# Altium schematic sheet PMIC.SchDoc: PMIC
size A3; Date: Not used; ApprovedBy: Not used; CheckedBy: Not used; Author: Not used; CompanyName: STMicroelectronics; DrawnBy: Not used; Engineer: Not used; Organization: Not used; Address1: Not used; Address2: Not used; Address3: Not used; Address4: Not used; DocumentNumber: 4; Revision: Not used; SheetNumber: 4; SheetTotal: 7
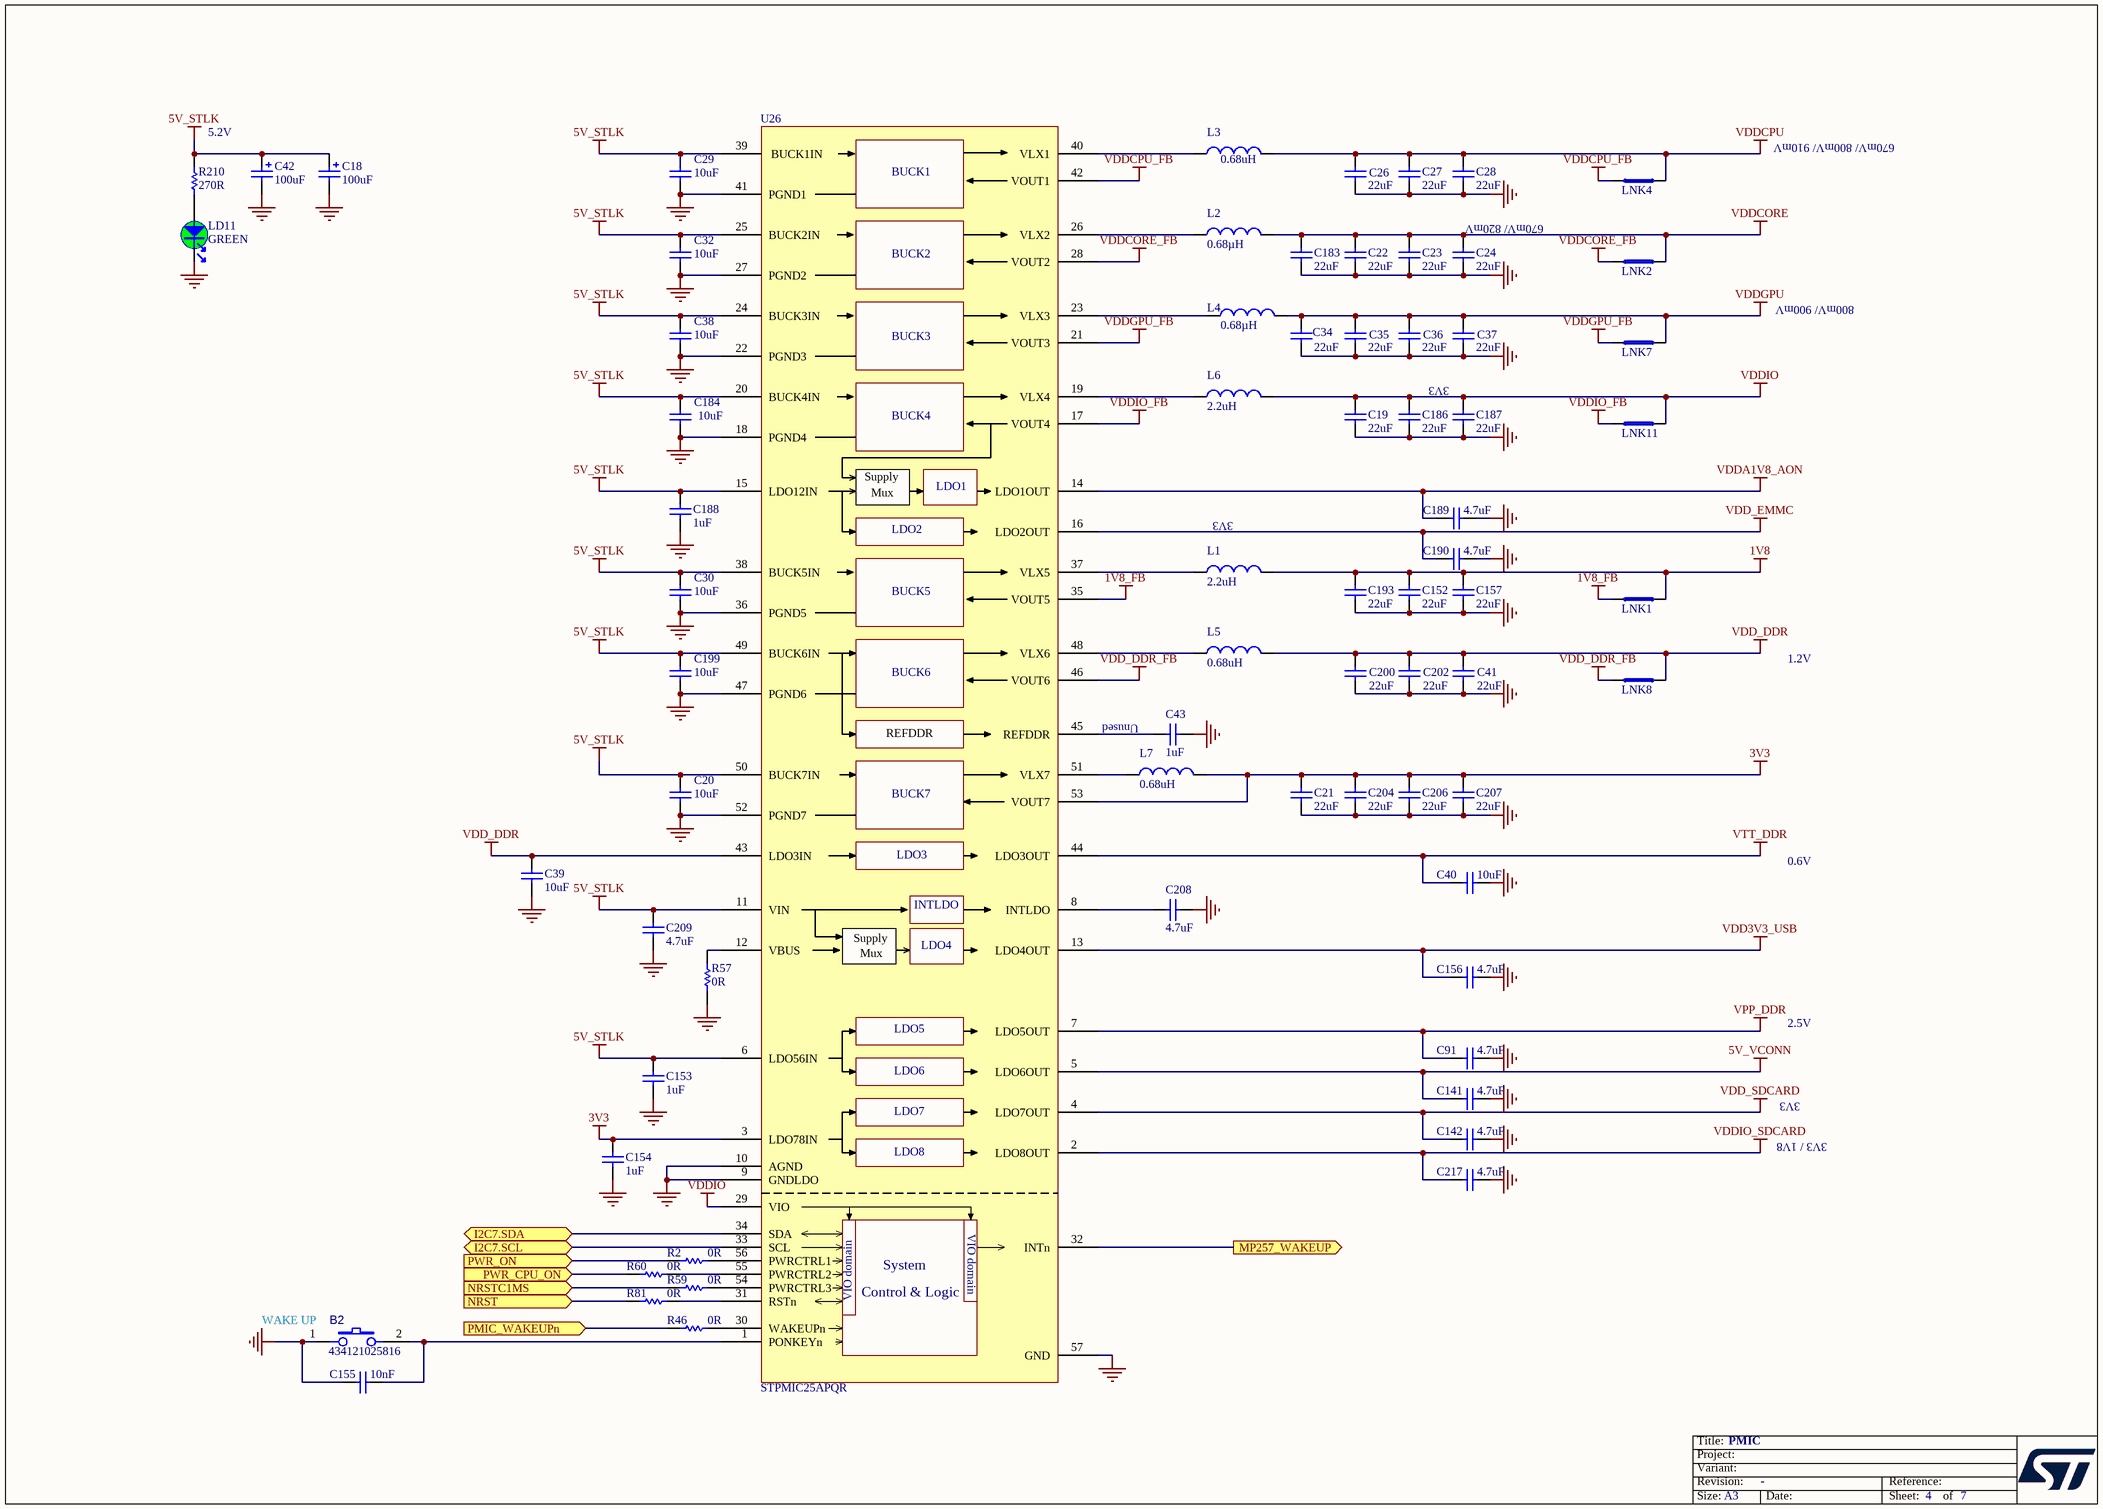
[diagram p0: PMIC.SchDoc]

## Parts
B2  value 434121025816  [SWI_WE_434121025816]  (hidden comment: SW_PUSH_SMD_2P)
C18  value 100uF  [CPOL_TCJ-B_1210_H210]  (hidden comment: Cap_POL_TANA)
C19  value 22uF  [C0805]  (hidden comment: Capacitor)
C20  value 10uF  [C0603]  (hidden comment: Capacitor)
C21  value 22uF  [C0805]  (hidden comment: Capacitor)
C22  value 22uF  [C0603]  (hidden comment: Capacitor)
C23  value 22uF  [C0603]  (hidden comment: Capacitor)
C24  value 22uF  [C0603]  (hidden comment: Capacitor)
C26  value 22uF  [C0603]  (hidden comment: Capacitor)
C27  value 22uF  [C0603]  (hidden comment: Capacitor)
C28  value 22uF  [C0603]  (hidden comment: Capacitor)
C29  value 10uF  [C0603]  (hidden comment: Capacitor)
C30  value 10uF  [C0603]  (hidden comment: Capacitor)
C32  value 10uF  [C0603]  (hidden comment: Capacitor)
C34  value 22uF  [C0603]  (hidden comment: Capacitor)
C35  value 22uF  [C0603]  (hidden comment: Capacitor)
C36  value 22uF  [C0603]  (hidden comment: Capacitor)
C37  value 22uF  [C0603]  (hidden comment: Capacitor)
C38  value 10uF  [C0603]  (hidden comment: Capacitor)
C39  value 10uF  [C0402]  (hidden comment: Capacitor)
C40  value 10uF  [C0402]  (hidden comment: Capacitor)
C41  value 22uF  [C0603]  (hidden comment: Capacitor)
C42  value 100uF  [CPOL_TCJ-B_1210_H210]  (hidden comment: Cap_POL_TANA)
C43  value 1uF  [C0402]  (hidden comment: Capacitor)
C91  value 4.7uF  [C0402]  (hidden comment: Capacitor)
C141  value 4.7uF  [C0402]  (hidden comment: Capacitor)
C142  value 4.7uF  [C0402]  (hidden comment: Capacitor)
C152  value 22uF  [C0805]  (hidden comment: Capacitor)
C153  value 1uF  [C0402]  (hidden comment: Capacitor)
C154  value 1uF  [C0402]  (hidden comment: Capacitor)
C155  value 10nF  [C0402]  (hidden comment: Capacitor)
C156  value 4.7uF  [C0402]  (hidden comment: Capacitor)
C157  value 22uF  [C0805]  (hidden comment: Capacitor)
C183  value 22uF  [C0603]  (hidden comment: Capacitor)
C184  value 10uF  [C0603]  (hidden comment: Capacitor)
C186  value 22uF  [C0805]  (hidden comment: Capacitor)
C187  value 22uF  [C0805]  (hidden comment: Capacitor)
C188  value 1uF  [C0402]  (hidden comment: Capacitor)
C189  value 4.7uF  [C0402]  (hidden comment: Capacitor)
C190  value 4.7uF  [C0402]  (hidden comment: Capacitor)
C193  value 22uF  [C0805]  (hidden comment: Capacitor)
C199  value 10uF  [C0603]  (hidden comment: Capacitor)
C200  value 22uF  [C0603]  (hidden comment: Capacitor)
C202  value 22uF  [C0603]  (hidden comment: Capacitor)
C204  value 22uF  [C0805]  (hidden comment: Capacitor)
C206  value 22uF  [C0805]  (hidden comment: Capacitor)
C207  value 22uF  [C0805]  (hidden comment: Capacitor)
C208  value 4.7uF  [C0402]  (hidden comment: Capacitor)
C209  value 4.7uF  [C0402]  (hidden comment: Capacitor)
C217  value 4.7uF  [C0402]  (hidden comment: Capacitor)
L1  value 2.2uH  [IND_2016_MURATA_LQM2MPN2R2NG0]  (hidden comment: Inductor)
L2  value 0.68µH  [IND_2520_TOKO_DFE252012P]  (hidden comment: Inductor)
L3  value 0.68uH  [IND_2016_MURATA_LQM2MPN2R2NG0]  (hidden comment: Inductor)
L4  value 0.68µH  [IND_2520_TOKO_DFE252012P]  (hidden comment: Inductor)
L5  value 0.68uH  [IND_2016_MURATA_LQM2MPN2R2NG0]  (hidden comment: Inductor)
L6  value 2.2uH  [IND_2016_MURATA_LQM2MPN2R2NG0]  (hidden comment: Inductor)
L7  value 0.68uH  [IND_2016_MURATA_LQM2MPN2R2NG0]  (hidden comment: Inductor)
LD11  value GREEN  [LED_0603_OSRAM_LG-Q396-PS-35_GREEN_1A2K_H0P4]  (hidden comment: LED_green)
LNK1  link_200  [LINK200]  (value not drawn)  (no BOM)
LNK2  link_200  [LINK200]  (value not drawn)  (no BOM)
LNK4  link_200  [LINK200]  (value not drawn)  (no BOM)
LNK7  link_200  [LINK200]  (value not drawn)  (no BOM)
LNK8  link_200  [LINK200]  (value not drawn)  (no BOM)
LNK11  link_200  [LINK200]  (value not drawn)  (no BOM)
R2  value 0R  [R0402]
R46  value 0R  [R0402]
R57  value 0R  [R0402]
R59  value 0R  [R0402]
R60  value 0R  [R0402]
R81  value 0R  [R0402]
R210  value 270R  [R0402]  (hidden comment: Resistor)
U26  STPMIC25APQR  [ICC_QFN56-EPAD_6P5X6P5_P040]

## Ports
I2C7.SCL (bidir), I2C7.SDA (bidir), MP257_WAKEUP (out), NRST (in), NRSTC1MS (in), PMIC_WAKEUPn (in), PWR_CPU_ON (in), PWR_ON (in)

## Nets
1V8: C152.2 C157.2 C193.2 L1.2 LNK1.2
1V8_FB: LNK1.1 U26.35(VOUT5)
3V3: C21.2 C154.2 C204.2 C206.2 C207.2 L7.2 U26.3(LDO78IN) U26.53(VOUT7)
5V_STLK: C18.1 C20.2 C29.2 C30.2 C32.2 C38.2 C42.1 C153.2 C184.2 C188.2 C199.2 C209.2 R210.1 U26.6(LDO56IN) U26.11(VIN) U26.15(LDO12IN) U26.20(BUCK4IN) U26.24(BUCK3IN) U26.25(BUCK2IN) U26.38(BUCK5IN) U26.39(BUCK1IN) U26.49(BUCK6IN) U26.50(BUCK7IN)
5V_VCONN: C141.1 U26.5(LDO6OUT)
GND: B2.1 C18.2 C19.1 C20.1 C21.1 C22.1 C23.1 C24.1 C26.1 C27.1 C28.1 C29.1 C30.1 C32.1 C34.1 C35.1 C36.1 C37.1 C38.1 C39.1 C40.1 C41.1 C42.2 C43.1 C91.2 C141.2 C142.2 C152.1 C153.1 C154.1 C155.1 C156.1 C157.1 C183.1 C184.1 C186.1 C187.1 C188.1 C189.1 C190.2 C193.1 C199.1 C200.1 C202.1 C204.1 C206.1 C207.1 C208.2 C209.1 C217.2 LD11.2 R57.1 U26.9(GNDLDO) U26.10(AGND) U26.18(PGND4) U26.22(PGND3) U26.27(PGND2) U26.36(PGND5) U26.41(PGND1) U26.47(PGND6) U26.52(PGND7) U26.57(GND)
VDD3V3_USB: C156.2 U26.13(LDO4OUT)
VDD_DDR: C39.2 C41.2 C200.2 C202.2 L5.2 LNK8.2 U26.43(LDO3IN)
VDD_DDR_FB: LNK8.1 U26.46(VOUT6)
VDD_EMMC: C190.1 U26.16(LDO2OUT)
VDD_SDCARD: C142.1 U26.4(LDO7OUT)
VDDA1V8_AON: C189.2 U26.14(LDO1OUT)
VDDCORE: C22.2 C23.2 C24.2 C183.2 L2.2 LNK2.2
VDDCORE_FB: LNK2.1 U26.28(VOUT2)
VDDCPU: C26.2 C27.2 C28.2 L3.2 LNK4.1
VDDCPU_FB: LNK4.2 U26.42(VOUT1)
VDDGPU: C34.2 C35.2 C36.2 C37.2 L4.2 LNK7.2
VDDGPU_FB: LNK7.1 U26.21(VOUT3)
VDDIO: C19.2 C186.2 C187.2 L6.2 LNK11.2 U26.29(VIO)
VDDIO_FB: LNK11.1 U26.17(VOUT4)
VDDIO_SDCARD: C217.1 U26.2(LDO8OUT)
VPP_DDR: C91.1 U26.7(LDO5OUT)
VTT_DDR: C40.2 U26.44(LDO3OUT)
I2C7.SCL: U26.33(SCL) ; port I2C7.SCL
I2C7.SDA: U26.34(SDA) ; port I2C7.SDA
MP257_WAKEUP: U26.32(INTn) ; port MP257_WAKEUP
NRST: R81.1 ; port NRST
NRSTC1MS: R59.1 ; port NRSTC1MS
PMIC_WAKEUPn: R46.1 ; port PMIC_WAKEUPn
PWR_CPU_ON: R60.1 ; port PWR_CPU_ON
PWR_ON: R2.1 ; port PWR_ON
NetB2_2: B2.2 C155.2 U26.1(PONKEYn)
NetC43_2: C43.2 U26.45(REFDDR)
NetC208_1: C208.1 U26.8(INTLDO)
NetL1_1: L1.1 U26.37(VLX5)
NetL2_1: L2.1 U26.26(VLX2)
NetL3_1: L3.1 U26.40(VLX1)
NetL4_1: L4.1 U26.23(VLX3)
NetL5_1: L5.1 U26.48(VLX6)
NetL6_1: L6.1 U26.19(VLX4)
NetL7_1: L7.1 U26.51(VLX7)
NetLD11_1: LD11.1 R210.2
NetR2_2: R2.2 U26.56(PWRCTRL1)
NetR46_2: R46.2 U26.30(WAKEUPn)
NetR57_2: R57.2 U26.12(VBUS)
NetR59_2: R59.2 U26.54(PWRCTRL3)
NetR60_2: R60.2 U26.55(PWRCTRL2)
NetR81_2: R81.2 U26.31(RSTn)

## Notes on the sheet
- 5.2V
- 670mV/ 800mV/ 910mV
- (near C24) 670mV/ 820mV
- 800mV/ 900mV
- 3V3
- (near L1) 3V3
- Unused
- 1.2V
- 0.6V
- 2.5V
- 3V3 / 1V8
- (near B2) WAKE UP

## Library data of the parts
B2 = MCD-03492: Switch tactile, SPST-NO, 50mA, 12V, 6x3.8mm; Part_Type: Misc; Part_Preference: Recommended; Manufacturer: WURTH ELEKTRONIK; Order_Code_RS: 1867991; Component_Country_Of_Origin: China; ShowFields: YES; ID: 5608
C18 C42 = MCD-01796: Capacitor, Tantalum, 100uF, 6V3, 40mR, +/-20%,  Type_B (3528 metric), T=1.9mm; Part_Preference: Recommended; Manufacturer: AVX; Manufacturer_Part_Number: TCJB107M006R0040; Component_Country_Of_Origin: Czech Republic; ShowFields: YES; ID: 3896
C19 C21 C152 C157 C186 C187 C193 C204 C206 C207 = MCD-03139: Capacitor, MLCC, 22uF, 10V, X5R, +/-20%, 0805, T=1,25mm; Part_Preference: Recommended; Manufacturer: MURATA; Manufacturer_Part_Number: GRM21BR61A226ME51L; ShowFields: YES; ID: 5255; Component_Country_Of_Origin: China, Japan
C20 C29 C30 C32 C38 C184 C199 = MCD-00099: Capacitor, MLCC, 10uF, 10V, X5R, +/-10%, 0603, T=0,8mm; Manufacturer_Part_Number: GRM188R61A106KE69D; Manufacturer: MURATA; Part_Preference: Recommended; Partial_Alternate_Internal_Part_Number: MCD-03152; Order_Code_RS: 2494233; Component_Country_Of_Origin: Japan°°; ID: 2770; ShowFields: YES
C22-C24 C26 C34-C37 C41 C200 C202 = MCD-00100: Capacitor, MLCC, 22uF, 6V3, X5R, +/-20%, 0603, T=0,8mm; Manufacturer_Part_Number: GRM188R60J226MEA0J; Manufacturer: MURATA; Part_Preference: Recommended; Component_Country_Of_Origin: Japan°°; ID: 2766; ShowFields: YES
C27 C28 C183 = MCD-00100: Capacitor, MLCC, 22uF, 6V3, X5R, +/-20%, 0603, T=0,8mm; Part_Preference: Recommended; Manufacturer: MURATA; Manufacturer_Part_Number: GRM188R60J226MEA0J; Component_Country_Of_Origin: Japan°°; ID: 2766; ShowFields: YES
C39 = MCD-03140: Capacitor, MLCC, 10uF, 6.3V, X5R, +/-20%, 0402, T=0.5mm; Part_Preference: Recommended; Manufacturer: MURATA; Manufacturer_Part_Number: GRM155R60J106ME05D; ShowFields: YES; ID: 5256
C40 = MCD-03140: Capacitor, MLCC, 10uF, 6.3V, X5R, +/-20%, 0402, T=0.5mm; Part_Preference: Recommended; Manufacturer: MURATA; Manufacturer_Part_Number: GRM155R60J106ME05D; ShowFields: YES; ID: 5256; Component_Country_Of_Origin: China, Japan
C43 C153 C154 C188 = MCD-00095: Capacitor, MLCC, 1uF, 25V, X5R, +/-10%, 0402, T=0.5mm; Part_Preference: Recommended; Manufacturer: MURATA; Manufacturer_Part_Number: GRM155R61E105KA12; Partial_Alternate_Internal_Part_Number: MCD-04188; Order_Code_RS: 2218855; Component_Country_Of_Origin: Japan°°; ShowFields: YES; ID: 2772
C91 C141 C142 C156 C189 C190 C208 C209 C217 = MCD-01356: Capacitor, MLCC, 4.7uF, 6V3, X5R, +/-20%, 0402, T=0.5mm; Manufacturer_Part_Number: GRM155R60J475ME47; Manufacturer: MURATA; Part_Preference: Recommended; Order_Code_RS: 814-5230; Component_Country_Of_Origin: Japan°°; ShowFields: YES; ID: 3456
C155 = MCD-02198: Capacitor, MLCC, 10nF, 50V, X7R, +/-10%, 0402, T=0.5mm; Manufacturer_Part_Number: CC0402KRX7R9BB103; Manufacturer: YAGEO; Part_Preference: Recommended; Order_Code_RS: 6169644; Component_Country_Of_Origin: China; ShowFields: YES; ID: 4298
L1 L6 = MCD-03143: Inductor, 2.2uH, +/-20%, Itemp= 1700mA, Isat= 2400mA, 0R140, 0806, T=1mm; Part_Preference: Recommended; Manufacturer: MURATA; Manufacturer_Part_Number: DFE201610E-2R2M=P2; ShowFields: YES; ID: 5259; Component_Country_Of_Origin: Vietnam
L2 L4 = MCD-03142: Inductor, 0.68uH, +/-20%, Itemp= 3900mA, Isat= 5400mA, 0R031, 1008, T=1.2mm; Part_Preference: Recommended; Manufacturer: MURATA; Manufacturer_Part_Number: DFE252012F-R68M=P2; ShowFields: YES; ID: 5258; Component_Country_Of_Origin: Vietnam
L3 L5 L7 = MCD-03141: Inductor, 0.68uH, +/-20%, Itemp= 3100mA, Isat= 4300mA, 0R043, 0806, T=1mm; Part_Preference: Recommended; Manufacturer: MURATA; Manufacturer_Part_Number: DFE201610E-R68M=P2; ShowFields: YES; ID: 5257; Component_Country_Of_Origin: Vietnam
LD11 = MCD-00588: LED Green, 0603 SMD, Forward Voltage Typ=2V, Max=2.5V; Part_Type: Display; Manufacturer_Part_Number: LG Q396-PS-35; Manufacturer: OSRAM OPTO SEMICONDUCTORS; Alternate_Manufacturer_Part_Number: VLMTG1300-GS08; Alternate_Manufacturer: VISHAY SEMICONDUCTOR OPTO DIVISION; Alternate_Internal_Part_Number: MCD-02400; Part_Preference: Recommended; Partial_Alternate_Internal_Part_Number: MCD-02400, MCD-03155, MCD-02901; Provided_By: SUBCO; Component_Country_Of_Origin: Unknown; ID: 3155; ShowFields: YES
LNK1 LNK2 LNK4 LNK7 LNK8 LNK11 = MCD-02777: Track link on PCB 200um width for layout routing; Part_Preference: Recommended; Part_Type: Misc; ID: 4889; ShowFields: YES; Component_Country_Of_Origin: Unknown
R2 R46 R57 R59 R60 R81 = MCD-00052: Resistor,0R,0402,5%,1/16W; Manufacturer_Part_Number: RC0402JR-070RL; Manufacturer: YAGEO; Part_Preference: Recommended; ECCN_US: EAR99; ECCN_EU: NEC; Provided_By: SUBCO; Initial_Board_Reference: mb1274; Order_Code_RS: 9232516RL; Component_Country_Of_Origin: China; ID: 2540; ShowFields: YES
R210 = MCD-00441: Resistor,270R,0402,1%,1/16W; Manufacturer_Part_Number: RC0402FR-07270RL; Manufacturer: YAGEO; Part_Preference: Recommended; Provided_By: SUBCO; ECCN_US: EAR99; ECCN_EU: NEC; Component_Country_Of_Origin: China; ID: 2838; ShowFields: YES
U26 = MCD-03000: STPMIC2; Part_Type: IC; Part_Preference: Recommended; Manufacturer: STMICROELECTRONICS; Component_Country_Of_Origin: Unknown; ShowFields: YES; ID: 5116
